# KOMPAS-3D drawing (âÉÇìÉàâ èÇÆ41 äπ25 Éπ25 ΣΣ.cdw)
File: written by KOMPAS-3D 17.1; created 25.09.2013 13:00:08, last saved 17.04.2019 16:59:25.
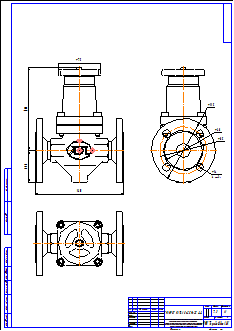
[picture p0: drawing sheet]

Sheet 1: A2, portrait

Title block, sheet 1: name: ГРАНРЕГ КАТ41 Ду25 Ру25 фф; material: Внимание! Данный продукт является объектом авторского права ООО «Торговый Дом АДЛ». / Запрещается изменение, копирование, распространение / (в том числе путем копирования на другие сайты и ресурсы в Интернете) / или любое иное использование информации и объектов без предварительного / согласия правообладателя (ООО «Торговый Дом АДЛ»).; mass: 7,3; sheets: 1; organisation: ООО "Торговый дом АДЛ"; sheet format: A2; stored path: \\adlc.lan\data\АДЛ_ПКД\3D-модели\ADL production\Клапаны КАТ ГРАНРЕГ\КАТ41\KOMPAS 2D\ГРАНРЕГ КАТ41 Ду25 Ру25 фф.cdw

Views: Вид 1, Проекционный вид 2
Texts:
  Klimkovich
  ADL
Dimensions and other numbers on the sheet: 75; 160; 150; 57,5; 115; 68; 85; 14; 4 отв.; 1:1; 1; 7,3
